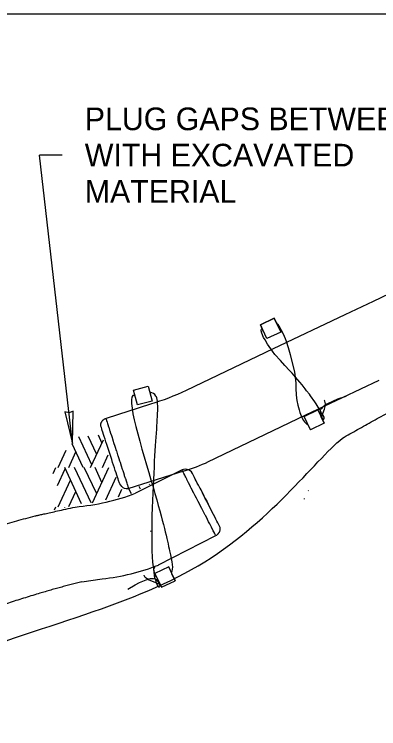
# Model space of a CAD drawing. Extents: x 99862 to 103680, y 99470 to 102076.
# Drawn here: x 100622 to 100880, y 101571 to 102076 of the extents above; entities that cross this region are included whole.
import ezdxf

# ---------------------------------------------------------------- set-up
doc = ezdxf.new("R2010")
doc.units = 0
for name, color, linetype in [('Level 1', 7, 'Continuous'), ('Level 10', 7, 'Continuous'), ('Level 11', 7, 'Continuous'), ('Level 15', 7, 'Continuous'), ('Level 17', 7, 'Continuous'), ('Level 20', 7, 'Continuous'), ('Level 4', 7, 'Continuous'), ('Level 6', 7, 'Continuous'), ('Level 8', 7, 'Continuous')]:
    doc.layers.add(name, color=color, linetype=linetype)

msp = doc.modelspace()

# ---------------------------------------------------------------- linework, layer by layer
at = {"layer": 'Level 1'}
msp.add_lwpolyline([(99862, 99999.5), (103151, 99999.5), (103151, 102075.5), (99862, 102075.5)], close=True, dxfattribs=at)
at = {"layer": 'Level 10'}
for p, q in [((100747.99, 101738.65), (100748.19, 101738.26)), ((100747.99, 101738.65), (100747.99, 101738.65)), ((100830, 101739.1), (100829.82, 101739.5)), ((100827.23, 101733.36), (100827.05, 101733.76)), ((100718.36, 101710.9), (100718.54, 101710.5)), ((100718.36, 101710.9), (100718.54, 101710.5))]:
    msp.add_line(p, q, dxfattribs=at)
at = {"layer": 'Level 11'}
for p, q in [((100680.45, 101764.94), (100674.4, 101777.87)), ((100684.17, 101772.99), (100681.68, 101778.45)), ((100670.84, 101755.77), (100663.13, 101772.43)), ((100670.84, 101770.65), (100667.76, 101777.35)), ((100676.21, 101755.77), (100685.23, 101775.27)), ((100653.37, 101755.77), (100658.94, 101767.99)), ((100676.99, 101757.5), (100670.84, 101770.65)), ((100660.72, 101755.77), (100665.74, 101766.76)), ((100684.51, 101755.77), (100688.66, 101764.67)), ((100649.71, 101751.42), (100651.72, 101755.77)), ((100652.69, 101742.85), (100658.21, 101754.82)), ((100669.79, 101730.1), (100657.95, 101755.68)), ((100670.84, 101742.71), (100664.87, 101755.68)), ((100680.45, 101737), (100671.71, 101755.68)), ((100677.57, 101730.78), (100689.1, 101755.68)), ((100684.17, 101745.04), (100679.32, 101755.68)), ((100686.86, 101732.87), (100694.27, 101748.78)), ((100653.37, 101727.83), (100662.02, 101746.77)), ((100676.46, 101730.68), (100670.84, 101742.71)), ((100711.46, 101740.28), (100710.51, 101742.33)), ((100718, 101743.45), (100717.82, 101743.84)), ((100660.85, 101728.1), (100665.74, 101738.81)), ((100695.82, 101735.04), (100698.28, 101740.33)), ((100704.87, 101737.24), (100703.43, 101740.34)), ((100704.64, 101737.18), (100704.76, 101737.43)), ((100650.77, 101725.76), (100651.72, 101727.83)), ((100658.08, 101727.46), (100657.95, 101727.74))]:
    msp.add_line(p, q, dxfattribs=at)
at = {"layer": 'Level 15'}
for p in [(100656.07, 101976.11), (100663.34, 101772.54)]:
    msp.add_line(p, (100640.07, 101976.11), dxfattribs=at)
msp.add_lwpolyline([(100663.3, 101772.51), (100663.97, 101795.52), (100661.1, 101794.17), (100658.03, 101794.92)], close=True, dxfattribs=at)
at = {"layer": 'Level 17'}
for points, degree in [([(100853.91, 101776.4), (100966.09, 101840.17), (101161.52, 101929.7)], 2), ([(100562.31, 101613.81), (100635.56, 101642.75), (100769.44, 101671.21), (100834.11, 101760.09), (100853.91, 101776.4)], 3)]:
    msp.add_open_spline(points, degree=degree, dxfattribs=at)
at = {"layer": 'Level 4'}
msp.add_line((100782.4, 101706.65), (100782.4, 101706.65), dxfattribs=at)
for points in [[(100856.26, 101805.81), (100850.51, 101803.79), (100847.43, 101802.54), (100842.85, 101800.28), (100841.25, 101799.25), (100840.41, 101798.61), (100839.18, 101797.4), (100838.78, 101796.85), (100838.29, 101795.81), (100838.15, 101794.88), (100838.41, 101793.31), (100839.01, 101791.43), (100839.36, 101790.63), (100840.05, 101789.86), (100840.54, 101789.78), (100840.75, 101789.87), (100840.97, 101790.18), (100840.91, 101791.07), (100840.34, 101792.3), (100839.92, 101793.04), (100839.18, 101794.26), (100838.39, 101795.55), (100838, 101796.21), (100836.83, 101798.27), (100835.45, 101800.55), (100834.51, 101801.98), (100833.33, 101803.68), (100832.63, 101804.64), (100831.44, 101806.24), (100830.56, 101807.4), (100828.62, 101809.88), (100827.58, 101811.2), (100825.38, 101813.92), (100823.85, 101815.77), (100820.71, 101819.48), (100818.36, 101822.17), (100816.63, 101824.09), (100813.29, 101827.73), (100810.15, 101831.14), (100806.31, 101835.52), (100804.56, 101837.7), (100801.13, 101842.59), (100799.29, 101845.65), (100798.3, 101847.49), (100796.94, 101850.49), (100796.51, 101852), (100796.48, 101852.55), (100796.77, 101853.36), (100797.21, 101853.77), (100797.21, 101853.77)], [(100807.15, 101858.02), (100807.2, 101857.99), (100807.72, 101857.38), (100808.06, 101856.91), (100808.96, 101855.61), (100810.55, 101853.07), (100811.44, 101851.42), (100812.83, 101848.42), (100813.53, 101846.68), (100814.22, 101844.76), (100815.59, 101840.4), (100816.99, 101835.32), (100820.14, 101822.93)], [(100820.14, 101822.93), (100820.84, 101817.5), (100820.99, 101814.94), (100821.02, 101813.55), (100821.01, 101811.12), (100821.21, 101807.28), (100821.51, 101804.69), (100821.78, 101802.96), (100822.46, 101799.58), (100823.31, 101796.37), (100823.95, 101794.38), (100825.35, 101790.87), (100826.49, 101788.76), (100827.07, 101787.91), (100828.23, 101786.67), (100828.8, 101786.32), (100829.44, 101786.18)], [(100839.14, 101790.93), (100839.67, 101792.37), (100840.05, 101793.68), (100841.19, 101796.86), (100841.7, 101798.74), (100841.9, 101800.58), (100841.82, 101801.44), (100841.49, 101802.47), (100841.2, 101802.92), (100841.02, 101803.1)], [(100702.46, 101669.86), (100707.72, 101672.92), (100710.67, 101674.45), (100715.37, 101676.46), (100717.19, 101677.01), (100718.22, 101677.23), (100719.93, 101677.38), (100720.62, 101677.33), (100721.73, 101677.02), (100722.53, 101676.53), (100723.55, 101675.31), (100724.58, 101673.63), (100724.96, 101672.85), (100725.11, 101671.82), (100724.85, 101671.4), (100724.64, 101671.29), (100724.27, 101671.33), (100723.63, 101671.96), (100723.06, 101673.18), (100722.77, 101673.98), (100722.33, 101675.34), (100721.86, 101676.78), (100721.61, 101677.5), (100721.26, 101679.73), (100720.96, 101681.57), (100720.83, 101683.82), (100721.42, 101685.49)], [(100724.52, 101673.3), (100723.08, 101673.83), (100721.83, 101674.4), (100718.68, 101675.6), (100716.92, 101676.43), (100715.39, 101677.48), (100714.78, 101678.09), (100714.22, 101679.02), (100714.06, 101679.53), (100714.05, 101679.68)]]:
    msp.add_lwpolyline(points, dxfattribs=at)
for points in [[(100706.95, 101806.58), (100699.95, 101808.15), (100725.36, 101727.44), (100732.6, 101693.51), (100734.78, 101684.13), (100732.94, 101681.42)], [(100723.14, 101677.87), (100718.32, 101680.61), (100720.25, 101752.5), (100724.47, 101799.99), (100722.49, 101806.92), (100720.13, 101808.31), (100718.07, 101808.9)]]:
    msp.add_open_spline(points, degree=3, dxfattribs=at)
at = {"layer": 'Level 6'}
for p, q in [((100805.74, 101860.99), (100795.99, 101856.34)), ((100795.99, 101856.33), (100805.74, 101860.98)), ((100805.74, 101860.99), (100805.74, 101860.98)), ((100808.05, 101856.13), (100805.74, 101860.99)), ((100805.74, 101860.99), (100805.74, 101860.98)), ((100805.74, 101860.98), (100810.38, 101851.26)), ((100795.99, 101856.33), (100795.99, 101856.34)), ((100795.99, 101856.34), (100798.31, 101851.48)), ((100795.99, 101856.34), (100795.99, 101856.34)), ((100800.63, 101846.61), (100795.99, 101856.33)), ((100810.38, 101851.26), (100800.63, 101846.61)), ((100810.38, 101851.26), (100810.38, 101851.26)), ((100800.63, 101846.61), (100800.63, 101846.61)), ((100706.4, 101810.23), (100716.83, 101813)), ((100716.83, 101813), (100719.61, 101802.57)), ((100709.18, 101799.79), (100706.4, 101810.23)), ((100717.52, 101812.54), (100717.52, 101812.54)), ((100719.61, 101802.57), (100709.18, 101799.79)), ((100836.58, 101796.29), (100826.83, 101791.64)), ((100841.09, 101786.84), (100838.77, 101791.7)), ((100829.02, 101787.06), (100831.34, 101782.19)), ((100841.08, 101786.85), (100831.34, 101782.2)), ((100731.3, 101685.51), (100721.52, 101680.93)), ((100735.88, 101675.73), (100731.3, 101685.51)), ((100721.52, 101680.93), (100726.1, 101671.15)), ((100735.88, 101675.72), (100733.6, 101680.6)), ((100733.6, 101680.6), (100735.88, 101675.73)), ((100726.1, 101671.14), (100735.88, 101675.72))]:
    msp.add_line(p, q, dxfattribs=at)
for points in [[(100805.74, 101860.99), (100808.05, 101856.13), (100808.05, 101856.13)], [(100805.74, 101860.99), (100805.74, 101860.99), (100805.74, 101860.99)], [(100798.31, 101851.48), (100798.31, 101851.48), (100795.99, 101856.34)], [(100795.99, 101856.34), (100795.99, 101856.34), (100795.99, 101856.34)], [(100836.58, 101796.29), (100841.08, 101786.85), (100841.09, 101786.84), (100831.34, 101782.19), (100831.34, 101782.2), (100826.83, 101791.64), (100836.58, 101796.29)], [(100836.58, 101796.29), (100836.58, 101796.29), (100841.09, 101786.84), (100841.09, 101786.84)], [(100831.34, 101782.2), (100831.34, 101782.2), (100826.83, 101791.64), (100826.83, 101791.64)], [(100838.77, 101791.7), (100841.09, 101786.84), (100841.09, 101786.84)], [(100831.34, 101782.2), (100831.34, 101782.2), (100829.02, 101787.06)]]:
    msp.add_lwpolyline(points, dxfattribs=at)
at = {"layer": 'Level 8'}
for p, q in [((100753.19, 101741.41), (100754.11, 101739.6)), ((100754.11, 101739.6), (100755.08, 101737.72)), ((100755.08, 101737.72), (100756.08, 101735.78)), ((100756.08, 101735.78), (100757.07, 101733.86)), ((100757.07, 101733.86), (100757.1, 101733.81)), ((100757.1, 101733.81), (100758.12, 101731.82)), ((100759.14, 101729.84), (100760.14, 101727.89)), ((100760.14, 101727.89), (100761.12, 101725.98)), ((100761.12, 101725.98), (100762.07, 101724.15))]:
    msp.add_line(p, q, dxfattribs=at)
for points in [[(100855.81, 101863.65), (100875.77, 101873.16), (100977.03, 101921.44)], [(100743.83, 101810.26), (100805.3, 101839.56), (100855.81, 101863.65)], [(100879.52, 101817.17), (100827.74, 101792.49), (100758.63, 101759.54)], [(100696.88, 101744.2), (100696.65, 101744.64), (100696.34, 101745.25), (100696.13, 101745.72), (100695.85, 101746.58), (100695.51, 101747.63), (100695.11, 101748.86), (100694.65, 101750.27), (100694.15, 101751.84), (100693.59, 101753.54), (100693, 101755.37), (100692.37, 101757.3), (100691.72, 101759.31), (100691.05, 101761.39), (100690.37, 101763.5), (100689.68, 101765.62), (100688.99, 101767.74), (100688.31, 101769.83), (100687.65, 101771.87), (100687.01, 101773.83), (100686.41, 101775.7), (100685.84, 101777.45), (100685.31, 101779.07), (100684.84, 101780.54), (100684.42, 101781.84), (100684.05, 101782.96), (100683.75, 101783.88), (100683.56, 101784.47), (100683.45, 101784.91), (100683.38, 101785.5), (100683.37, 101785.62), (100683.37, 101785.77), (100683.43, 101786.48), (100683.45, 101786.56), (100683.62, 101787.18), (100683.67, 101787.32), (100683.8, 101787.59), (100683.99, 101787.98), (100684.38, 101788.56), (100684.42, 101788.61), (100684.52, 101788.73), (100685.06, 101789.29), (100685.19, 101789.39), (100685.68, 101789.78), (100685.82, 101789.87), (100686.17, 101790.06), (100686.52, 101790.26), (100687.27, 101790.56), (100718.59, 101800.63)], [(100686.89, 101790.41), (100686.98, 101790.13), (100687.36, 101788.98), (100687.41, 101788.81), (100687.81, 101787.58), (100688.08, 101786.76), (100688.34, 101785.95), (100688.87, 101784.31), (100688.93, 101784.12), (100689.59, 101782.1), (100689.79, 101781.47), (100690.3, 101779.91), (100690.81, 101778.33), (100691.05, 101777.57), (100691.85, 101775.12), (100691.9, 101774.95), (100692.68, 101772.57), (100693.06, 101771.39), (100693.52, 101769.96), (100694.25, 101767.73), (100694.38, 101767.31), (100695.24, 101764.65), (100695.44, 101764.04), (100696.1, 101762.01), (100696.62, 101760.4), (100696.94, 101759.42), (100697.76, 101756.91), (100698.54, 101754.49), (100698.84, 101753.58), (100699.28, 101752.21), (100699.83, 101750.52), (100699.97, 101750.08), (100700.61, 101748.12), (100700.71, 101747.8), (100701.18, 101746.36), (100701.46, 101745.48), (100701.68, 101744.81), (100702.09, 101743.55), (100702.1, 101743.5), (100702.45, 101742.43), (100702.54, 101742.15), (100702.71, 101741.63), (100702.84, 101741.23), (100702.89, 101741.08), (100702.98, 101740.81)], [(100742.38, 101753.35), (100702.51, 101740.5)], [(100741.81, 101754.35), (100740.68, 101753.93), (100707.95, 101737.44)], [(100764.51, 101707.6), (100764.38, 101707.86), (100763.82, 101708.94), (100763.74, 101709.09), (100763.15, 101710.25), (100762.75, 101711.02), (100762.37, 101711.76), (100761.58, 101713.3), (100761.48, 101713.48), (100760.51, 101715.37), (100760.21, 101715.95), (100759.46, 101717.42), (100758.7, 101718.89), (100758.33, 101719.6), (100757.15, 101721.89), (100757.08, 101722.05), (100755.93, 101724.27), (100755.36, 101725.38), (100754.67, 101726.72), (100753.6, 101728.8), (100753.4, 101729.19), (100752.12, 101731.68), (100751.82, 101732.25), (100750.85, 101734.14), (100750.07, 101735.65), (100749.6, 101736.57), (100748.39, 101738.92), (100747.23, 101741.17), (100746.79, 101742.03), (100746.13, 101743.31), (100745.32, 101744.89), (100745.11, 101745.3), (100744.17, 101747.13), (100744.01, 101747.43), (100743.32, 101748.78), (100742.9, 101749.6), (100742.58, 101750.22), (100741.97, 101751.4), (100741.95, 101751.45), (100741.43, 101752.45), (100741.3, 101752.71), (100741.04, 101753.2), (100740.85, 101753.58), (100740.78, 101753.71), (100740.65, 101753.96)], [(100747.97, 101751.54), (100747.29, 101752.53), (100746.41, 101753.36), (100745.36, 101753.96), (100744.21, 101754.32), (100743, 101754.41), (100741.81, 101754.35)], [(100724.2, 101686.86), (100764.51, 101707.6), (100765.2, 101708.02), (100765.51, 101708.27), (100765.83, 101708.51), (100765.95, 101708.63), (100766.37, 101709.09), (100766.49, 101709.21), (100766.93, 101709.84), (100767.01, 101709.98), (100767.04, 101710.04), (100767.33, 101710.67), (100767.45, 101711.08), (100767.54, 101711.38), (100767.57, 101711.52), (100767.63, 101712.16), (100767.64, 101712.25), (100767.59, 101712.96), (100767.56, 101713.11), (100767.53, 101713.21), (100767.37, 101713.79), (100767.18, 101714.2), (100766.9, 101714.75), (100766.46, 101715.62), (100765.92, 101716.66), (100765.29, 101717.88), (100764.59, 101719.25), (100763.81, 101720.76), (100762.97, 101722.4), (100762.07, 101724.15), (100761.12, 101725.98), (100760.14, 101727.89), (100759.14, 101729.84), (100758.12, 101731.82), (100757.1, 101733.81), (100756.08, 101735.78), (100755.08, 101737.72), (100754.11, 101739.6), (100753.19, 101741.41), (100752.31, 101743.12), (100751.49, 101744.71), (100750.73, 101746.17), (100750.06, 101747.49), (100749.46, 101748.64), (100748.96, 101749.63), (100748.55, 101750.42), (100748.23, 101751.03), (100748.03, 101751.43), (100747.92, 101751.64)], [(100702.51, 101740.5), (100701.3, 101740.53), (100700.13, 101740.83), (100699.05, 101741.38), (100698.12, 101742.15), (100697.39, 101743.11), (100696.88, 101744.2)], [(100758.12, 101731.82), (100758.57, 101730.95), (100759.14, 101729.84)], [(100669.86, 101674.95), (100684.27, 101677.06)]]:
    msp.add_lwpolyline(points, dxfattribs=at)
for centre, radius, start, end in [((100671.93, 101960.87), 166.89, 286.2326, 295.5163), ((100712.51, 101857.13), 108, 286.0586, 295.6739)]:
    msp.add_arc(centre, radius, start, end, dxfattribs=at)
for centre, major_axis, ratio, start_param, end_param in [((100649.4, 101824.19), (130.13, 0), 0.746461, 4.834507, 5.179106), ((100665.78, 101773.8), (127.68, 0), 0.765805, 4.85769, 5.187618)]:
    msp.add_ellipse(centre, major_axis=major_axis, ratio=ratio, start_param=start_param, end_param=end_param, dxfattribs=at)
for points in [[(100636.98, 101721.51), (100636.98, 101721.51), (100665.25, 101727.75)], [(100537.59, 101688.43), (100585.52, 101708.09), (100636.98, 101721.51)], [(100669.86, 101674.95), (100636.74, 101666.83), (100595.83, 101652.37)]]:
    msp.add_open_spline(points, degree=2, dxfattribs=at)

# ---------------------------------------------------------------- texts
at = {"layer": 'Level 20'}
for s, p in [('PLUG GAPS BETWEEN LOGS ', (100672.07, 101993.71)), ('WITH EXCAVATED ', (100672.07, 101968.11)), ('MATERIAL', (100672.07, 101942.51))]:
    msp.add_text(s, height=16, dxfattribs=at).set_placement(p)

doc.saveas('drawing.dxf')
